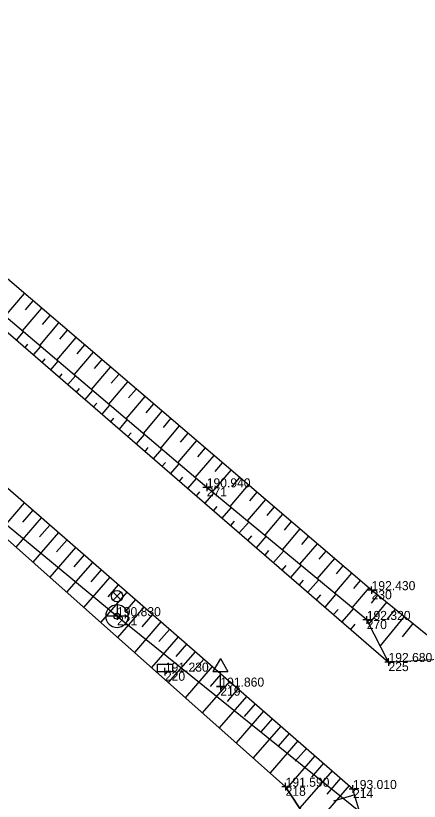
# Model space of a CAD drawing. Extents: x -744883 to -744469, y -966832 to -966374.
# Drawn here: x -744817.1 to -744790.4, y -966598.7 to -966546.7 of the extents above; entities that cross this region are included whole.
import ezdxf

# ---------------------------------------------------------------- set-up
doc = ezdxf.new("R2010")
doc.units = 0
for name, color, linetype in [('Body - výška', 7, 'Continuous'), ('Body - značka', 7, 'Continuous'), ('Body - číslo', 7, 'Continuous'), ('Body polohopisu', 7, 'Continuous'), ('Doplňkové značky', 7, 'Continuous'), ('Ploty_opěrné zdi', 7, 'Continuous'), ('Rozhraní ploch', 7, 'Continuous'), ('Vrstva 132', 7, 'Continuous'), ('Výškopis', 7, 'Continuous'), ('Výšky bodů', 7, 'Continuous'), ('Značky IS', 7, 'Continuous'), ('Čísla bodů', 7, 'Continuous')]:
    doc.layers.add(name, color=color, linetype=linetype)

msp = doc.modelspace()

# ---------------------------------------------------------------- linework, layer by layer
at = {"layer": 'Body - značka'}
for q in [(-744807.2, -966589.83), (-744807.45, -966590.08), (-744806.95, -966590.08), (-744807.2, -966590.33)]:
    msp.add_line((-744807.2, -966590.08), q, dxfattribs=at)
at = {"layer": 'Body polohopisu'}
for p, q in [((-744804.43, -966577.89), (-744804.68, -966577.89)), ((-744804.43, -966577.89), (-744804.43, -966577.64)), ((-744804.43, -966577.89), (-744804.18, -966577.89)), ((-744804.43, -966577.89), (-744804.43, -966578.14)), ((-744793.52, -966584.69), (-744793.52, -966584.44)), ((-744793.52, -966584.69), (-744793.77, -966584.69)), ((-744793.52, -966584.69), (-744793.27, -966584.69)), ((-744793.52, -966584.69), (-744793.52, -966584.94)), ((-744810.37, -966586.41), (-744810.37, -966586.16)), ((-744810.37, -966586.41), (-744810.62, -966586.41)), ((-744810.37, -966586.41), (-744810.12, -966586.41)), ((-744810.37, -966586.41), (-744810.37, -966586.66)), ((-744793.84, -966586.66), (-744794.09, -966586.66)), ((-744793.84, -966586.66), (-744793.84, -966586.41)), ((-744793.84, -966586.66), (-744793.59, -966586.66)), ((-744793.84, -966586.66), (-744793.84, -966586.91)), ((-744792.4, -966589.44), (-744792.4, -966589.19)), ((-744792.4, -966589.44), (-744792.65, -966589.44)), ((-744792.4, -966589.44), (-744792.15, -966589.44)), ((-744792.4, -966589.44), (-744792.4, -966589.69)), ((-744803.53, -966591.07), (-744803.53, -966590.82)), ((-744803.53, -966591.07), (-744803.78, -966591.07)), ((-744803.53, -966591.07), (-744803.28, -966591.07)), ((-744803.53, -966591.07), (-744803.53, -966591.32)), ((-744799.21, -966597.69), (-744799.21, -966597.44)), ((-744794.75, -966597.84), (-744794.75, -966597.59)), ((-744799.21, -966597.69), (-744799.46, -966597.69)), ((-744799.21, -966597.69), (-744798.96, -966597.69)), ((-744799.21, -966597.69), (-744799.21, -966597.94)), ((-744794.75, -966597.84), (-744795, -966597.84)), ((-744794.75, -966597.84), (-744794.5, -966597.84)), ((-744794.75, -966597.84), (-744794.75, -966598.09))]:
    msp.add_line(p, q, dxfattribs=at)
at = {"layer": 'Doplňkové značky'}
for p, q in [((-744810.634, -966585.348), (-744810.106, -966584.82)), ((-744810.098, -966585.345), (-744810.626, -966584.816)), ((-744810.37, -966585.46), (-744810.37, -966586.21)), ((-744803.53, -966589.204), (-744804.03, -966590.07)), ((-744803.53, -966589.204), (-744803.03, -966590.07)), ((-744804.03, -966590.07), (-744803.03, -966590.07)), ((-744803.53, -966591.07), (-744803.53, -966590.07)), ((-744803.78, -966591.07), (-744803.28, -966591.07))]:
    msp.add_line(p, q, dxfattribs=at)
for centre, radius in [((-744810.37, -966585.085), 0.375), ((-744810.37, -966586.41), 0.2)]:
    msp.add_circle(centre, radius, dxfattribs=at)
at = {"layer": 'Ploty_opěrné zdi'}
for points in [[(-744789.82, -966587.68), (-744793.52, -966584.69), (-744821.31, -966560.97)], [(-744797.83, -966608.07), (-744796.56, -966601.68), (-744799.21, -966597.69), (-744825.83, -966574.07), (-744838.86, -966562.47)]]:
    msp.add_lwpolyline(points, dxfattribs=at)
at = {"layer": 'Rozhraní ploch'}
for points in [[(-744823.64, -966560.07), (-744824.49, -966561.26), (-744822.69, -966563.25), (-744792.4, -966589.44), (-744789.07, -966589.25), (-744787.02, -966587.43), (-744786.08, -966585.59), (-744781.44, -966572.53), (-744776.99, -966559.6), (-744773.56, -966547.49), (-744770.22, -966529.59), (-744766.93, -966517.4), (-744763.66, -966508.11), (-744759.7, -966498.38), (-744760.87, -966499.15)], [(-744809.65, -966624.01), (-744794.4, -966605.79), (-744793.4, -966602.41), (-744794.75, -966597.84), (-744825.34, -966571.24), (-744838.68, -966559.82), (-744847.92, -966551.74), (-744849.33, -966553.16)]]:
    msp.add_lwpolyline(points, dxfattribs=at)
at = {"layer": 'Vrstva 132'}
msp.add_lwpolyline([(-744877.13, -966529.66), (-744852.31, -966550.13), (-744834.41, -966566.54), (-744810.37, -966586.41), (-744784.17, -966607.48)], dxfattribs=at)
at = {"layer": 'Výškopis'}
for points in [[(-744797.83, -966608.07), (-744794.4, -966605.79), (-744793.4, -966602.41), (-744794.75, -966597.84), (-744825.34, -966571.24), (-744838.68, -966559.82), (-744847.92, -966551.74)], [(-744848.47, -966552.52), (-744840.41, -966559.08), (-744838.86, -966562.47), (-744825.83, -966574.07), (-744799.21, -966597.69), (-744796.56, -966601.68), (-744797.83, -966608.07)], [(-744792.4, -966589.44), (-744793.84, -966586.66), (-744804.43, -966577.89), (-744820.81, -966564)], [(-744816.519, -966565.059), (-744817.796, -966566.556)], [(-744815.949, -966565.546), (-744816.459, -966566.144)], [(-744815.378, -966566.033), (-744816.652, -966567.526)], [(-744814.808, -966566.52), (-744815.317, -966567.116)], [(-744814.237, -966567.007), (-744815.508, -966568.496)], [(-744813.667, -966567.494), (-744814.175, -966568.089)], [(-744817.023, -966568.15), (-744816.555, -966567.608)], [(-744813.096, -966567.981), (-744814.364, -966569.466)], [(-744816.456, -966568.64), (-744816.267, -966568.421)], [(-744812.526, -966568.468), (-744813.032, -966569.061)], [(-744815.889, -966569.131), (-744815.411, -966568.578)], [(-744811.956, -966568.954), (-744813.22, -966570.436)], [(-744815.321, -966569.621), (-744815.128, -966569.398)], [(-744814.754, -966570.112), (-744814.267, -966569.549)], [(-744811.385, -966569.441), (-744811.89, -966570.033)], [(-744810.815, -966569.928), (-744812.076, -966571.406)], [(-744814.187, -966570.602), (-744813.99, -966570.375)], [(-744813.619, -966571.093), (-744813.123, -966570.519)], [(-744810.244, -966570.415), (-744810.748, -966571.006)], [(-744809.674, -966570.902), (-744810.932, -966572.376)], [(-744813.052, -966571.584), (-744812.851, -966571.352)], [(-744812.485, -966572.074), (-744811.979, -966571.489)], [(-744809.103, -966571.389), (-744809.606, -966571.978)], [(-744808.533, -966571.876), (-744809.788, -966573.347)], [(-744811.917, -966572.565), (-744811.713, -966572.328)], [(-744811.35, -966573.055), (-744810.834, -966572.459)], [(-744807.962, -966572.363), (-744808.464, -966572.95)], [(-744807.392, -966572.85), (-744808.644, -966574.317)], [(-744810.783, -966573.546), (-744810.575, -966573.305)], [(-744810.215, -966574.036), (-744809.69, -966573.429)], [(-744806.821, -966573.337), (-744807.322, -966573.923)], [(-744806.251, -966573.824), (-744807.5, -966575.287)], [(-744809.648, -966574.527), (-744809.436, -966574.282)], [(-744809.081, -966575.017), (-744808.546, -966574.399)], [(-744805.681, -966574.31), (-744806.179, -966574.895)], [(-744808.513, -966575.508), (-744808.298, -966575.259)], [(-744805.11, -966574.797), (-744806.356, -966576.257)], [(-744804.54, -966575.284), (-744805.037, -966575.867)], [(-744807.946, -966575.998), (-744807.402, -966575.37)], [(-744803.969, -966575.771), (-744805.212, -966577.227)], [(-744807.379, -966576.489), (-744807.159, -966576.235)], [(-744803.399, -966576.258), (-744803.895, -966576.84)], [(-744806.811, -966576.979), (-744806.258, -966576.34)], [(-744802.828, -966576.745), (-744804.064, -966578.193)], [(-744806.244, -966577.47), (-744806.021, -966577.212)], [(-744805.677, -966577.961), (-744805.114, -966577.31)], [(-744802.258, -966577.232), (-744802.749, -966577.808)], [(-744801.687, -966577.719), (-744802.909, -966579.15)], [(-744805.109, -966578.451), (-744804.882, -966578.189)], [(-744804.542, -966578.942), (-744803.965, -966578.275)], [(-744801.117, -966578.206), (-744801.603, -966578.775)], [(-744816.514, -966578.915), (-744818.193, -966580.846)], [(-744800.546, -966578.693), (-744801.753, -966580.107)], [(-744815.948, -966579.407), (-744816.622, -966580.182)], [(-744803.975, -966579.432), (-744803.74, -966579.161)], [(-744803.407, -966579.923), (-744802.81, -966579.232)], [(-744799.976, -966579.18), (-744800.456, -966579.742)], [(-744815.382, -966579.899), (-744817.071, -966581.842)], [(-744799.405, -966579.666), (-744800.598, -966581.063)], [(-744814.816, -966580.391), (-744815.494, -966581.171)], [(-744802.84, -966580.413), (-744802.597, -966580.132)], [(-744802.273, -966580.904), (-744801.654, -966580.189)], [(-744798.835, -966580.153), (-744799.309, -966580.709)], [(-744814.25, -966580.883), (-744815.949, -966582.837)], [(-744798.265, -966580.64), (-744799.443, -966582.02)], [(-744813.684, -966581.376), (-744814.366, -966582.159)], [(-744801.705, -966581.394), (-744801.454, -966581.103)], [(-744801.138, -966581.885), (-744800.499, -966581.146)], [(-744797.694, -966581.127), (-744798.162, -966581.676)], [(-744813.118, -966581.868), (-744814.827, -966583.833)], [(-744797.124, -966581.614), (-744798.287, -966582.977)], [(-744812.552, -966582.36), (-744813.238, -966583.148)], [(-744800.571, -966582.375), (-744800.311, -966582.075)], [(-744800.003, -966582.866), (-744799.343, -966582.103)], [(-744796.553, -966582.101), (-744797.016, -966582.643)], [(-744811.986, -966582.852), (-744813.705, -966584.829)], [(-744799.436, -966583.357), (-744799.168, -966583.046)], [(-744798.869, -966583.847), (-744798.188, -966583.06)], [(-744795.983, -966582.588), (-744797.132, -966583.934)], [(-744795.412, -966583.075), (-744795.869, -966583.61)], [(-744811.42, -966583.344), (-744812.11, -966584.137)], [(-744794.842, -966583.562), (-744795.976, -966584.891)], [(-744810.854, -966583.836), (-744812.583, -966585.824)], [(-744798.301, -966584.338), (-744798.025, -966584.018)], [(-744797.734, -966584.828), (-744797.032, -966584.017)], [(-744794.271, -966584.049), (-744794.722, -966584.577)], [(-744810.288, -966584.328), (-744810.982, -966585.126)], [(-744793.701, -966584.536), (-744794.821, -966585.848)], [(-744809.722, -966584.821), (-744811.461, -966586.82)], [(-744797.167, -966585.319), (-744796.882, -966584.989)], [(-744796.599, -966585.809), (-744795.877, -966584.973)], [(-744793.122, -966585.012), (-744793.556, -966585.549)], [(-744809.156, -966585.313), (-744809.854, -966586.115)], [(-744792.538, -966585.483), (-744793.703, -966586.924)], [(-744808.59, -966585.805), (-744810.339, -966587.815)], [(-744796.032, -966586.3), (-744795.739, -966585.961)], [(-744795.464, -966586.79), (-744794.721, -966585.93)], [(-744791.955, -966585.955), (-744792.504, -966586.633)], [(-744808.024, -966586.297), (-744808.726, -966587.103)], [(-744791.372, -966586.426), (-744792.95, -966588.379)], [(-744807.459, -966586.789), (-744809.217, -966588.811)], [(-744794.897, -966587.281), (-744794.596, -966586.932)], [(-744790.788, -966586.897), (-744791.502, -966587.781)], [(-744806.893, -966587.281), (-744807.598, -966588.092)], [(-744806.327, -966587.773), (-744808.095, -966589.807)], [(-744805.761, -966588.266), (-744806.47, -966589.081)], [(-744805.195, -966588.758), (-744806.973, -966590.802)], [(-744804.629, -966589.25), (-744805.342, -966590.07)], [(-744804.063, -966589.742), (-744805.851, -966591.798)], [(-744803.497, -966590.234), (-744804.214, -966591.059)], [(-744802.931, -966590.726), (-744804.729, -966592.793)], [(-744802.365, -966591.218), (-744803.086, -966592.047)], [(-744801.799, -966591.71), (-744803.606, -966593.789)], [(-744801.233, -966592.203), (-744801.958, -966593.036)], [(-744800.667, -966592.695), (-744802.484, -966594.785)], [(-744800.101, -966593.187), (-744800.83, -966594.025)], [(-744799.535, -966593.679), (-744801.362, -966595.78)], [(-744798.969, -966594.171), (-744799.702, -966595.014)], [(-744798.403, -966594.663), (-744800.24, -966596.776)], [(-744797.837, -966595.155), (-744798.574, -966596.003)], [(-744797.271, -966595.648), (-744799.14, -966597.796)], [(-744796.705, -966596.14), (-744797.507, -966597.061)], [(-744796.139, -966596.632), (-744798.279, -966599.092)], [(-744795.008, -966597.616), (-744797.418, -966600.388)], [(-744795.573, -966597.124), (-744796.483, -966598.17)], [(-744794.634, -966598.232), (-744796.044, -966598.648)]]:
    msp.add_lwpolyline(points, dxfattribs=at)
at = {"layer": 'Značky IS'}
msp.add_line((-744809.623, -966586.41), (-744811.118, -966586.41), dxfattribs=at)
msp.add_lwpolyline([(-744807.7, -966590.08), (-744807.7, -966589.58), (-744806.7, -966589.58), (-744806.7, -966590.08)], close=True, dxfattribs=at)
for start, end in [(0, 180), (180, 0)]:
    msp.add_arc((-744810.37, -966586.41), 0.747, start, end, dxfattribs=at)

# ---------------------------------------------------------------- texts
at = {"layer": 'Body - výška'}
msp.add_text('191.230', height=0.6, dxfattribs=at).set_placement((-744807.2, -966590.08))
at = {"layer": 'Body - číslo'}
msp.add_text('220', height=0.6, dxfattribs=at).set_placement((-744807.2, -966590.68))
at = {"layer": 'Výšky bodů'}
for s, p in [('190.940', (-744804.43, -966577.89)), ('192.430', (-744793.52, -966584.69)), ('190.830', (-744810.37, -966586.41)), ('192.320', (-744793.84, -966586.66)), ('192.680', (-744792.4, -966589.44)), ('191.860', (-744803.53, -966591.07)), ('191.590', (-744799.21, -966597.69)), ('193.010', (-744794.75, -966597.84))]:
    msp.add_text(s, height=0.6, dxfattribs=at).set_placement(p)
at = {"layer": 'Čísla bodů'}
for s, p in [('271', (-744804.43, -966578.49)), ('230', (-744793.52, -966585.29)), ('221', (-744810.37, -966587.01)), ('270', (-744793.84, -966587.26)), ('225', (-744792.4, -966590.04)), ('219', (-744803.53, -966591.67)), ('218', (-744799.21, -966598.29)), ('214', (-744794.75, -966598.44))]:
    msp.add_text(s, height=0.6, dxfattribs=at).set_placement(p)

doc.saveas('drawing.dxf')
